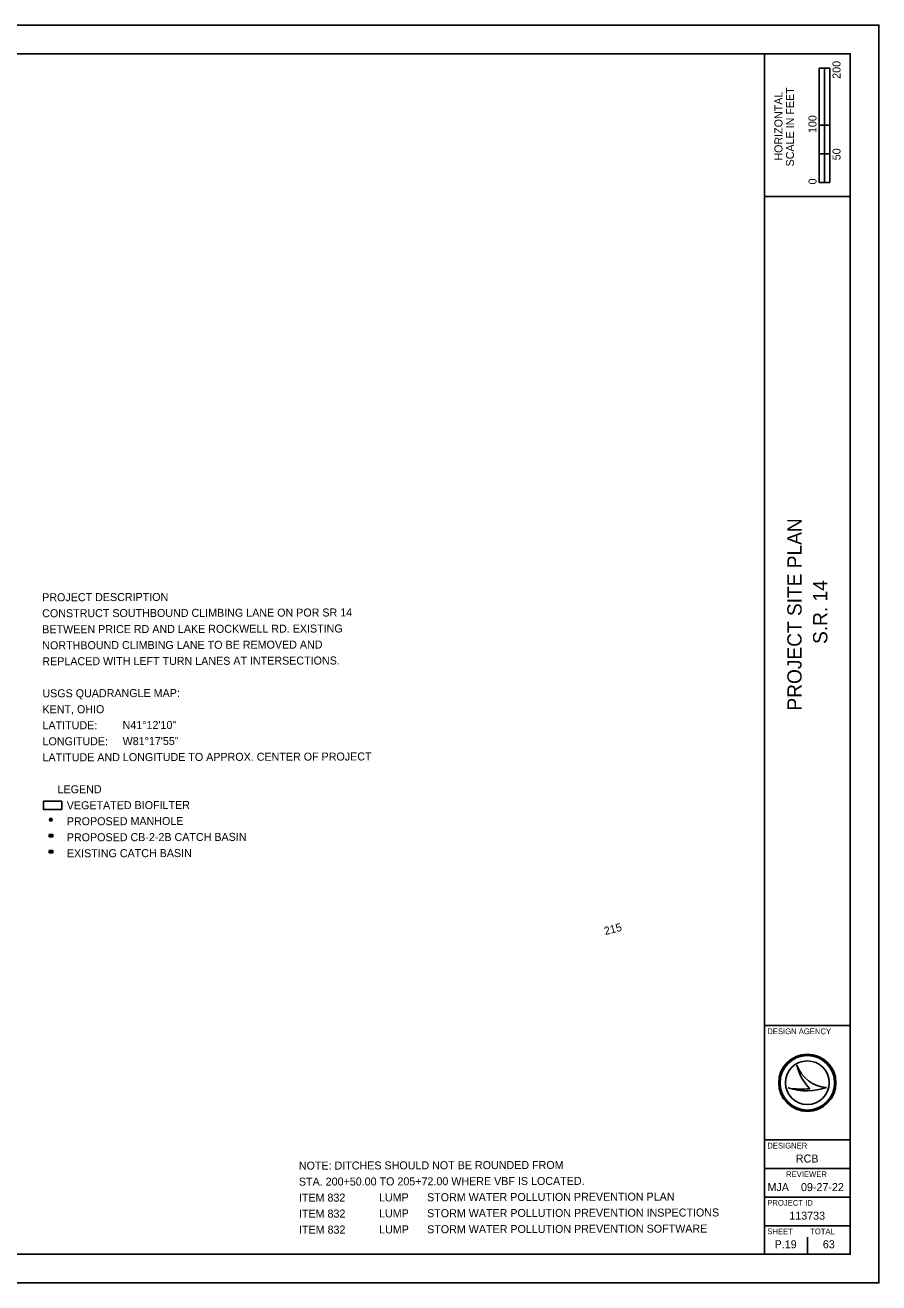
# Model space of a CAD drawing. Extents: x -4.7 to 34, y -1.1 to 22.
# Drawn here: x 19.07 to 34, y 0 to 22 of the extents above; entities that cross this region are included whole.
import ezdxf

# ---------------------------------------------------------------- set-up
doc = ezdxf.new("R2010")
doc.units = 0
for name, color, linetype in [('_CIVIL_CONSTRUCTION', 7, 'Continuous'), ('RW_X_CL_1000_Bearings', 7, 'Continuous'), ('RW_X_CL_1000_Cardinal_Points', 7, 'Continuous'), ('RW_X_CL_1000_Curve_Data', 7, 'Continuous'), ('RW_X_CL_100_Bearings', 7, 'Continuous'), ('RW_X_CL_100_Cardinal_Points', 7, 'Continuous'), ('RW_X_CL_500_Bearings', 7, 'Continuous'), ('RW_X_CL_500_Stations', 7, 'Continuous')]:
    doc.layers.add(name, color=color, linetype=linetype)

msp = doc.modelspace()

# ---------------------------------------------------------------- linework, layer by layer
at = {"layer": '_CIVIL_CONSTRUCTION'}
msp.add_lwpolyline([(0, 0), (34, 0), (34, 22), (0, 22)], close=True, dxfattribs=at)
at = {"layer": 'RW_X_CL_1000_Bearings'}
for p, q in [((19.499, 7.526), (19.531, 7.558)), ((19.499, 7.538), (19.52, 7.558)), ((19.499, 7.549), (19.509, 7.558)), ((19.51, 7.526), (19.542, 7.558)), ((19.521, 7.526), (19.553, 7.557)), ((19.533, 7.526), (19.553, 7.546)), ((19.544, 7.526), (19.553, 7.535))]:
    msp.add_line(p, q, dxfattribs=at)
for points in [[(19.493, 7.562), (19.559, 7.562), (19.559, 7.522), (19.493, 7.522)], [(19.499, 7.558), (19.553, 7.558), (19.553, 7.526), (19.499, 7.526)], [(19.499, 7.555), (19.553, 7.555), (19.553, 7.529), (19.499, 7.529)]]:
    msp.add_lwpolyline(points, close=True, dxfattribs=at)
at = {"layer": 'RW_X_CL_1000_Cardinal_Points'}
for p, q in [((19.524, 8.122), (19.524, 8.122)), ((19.524, 8.102), (19.524, 8.102)), ((19.524, 8.102), (19.524, 8.102)), ((19.524, 8.095), (19.524, 8.095)), ((19.524, 8.082), (19.524, 8.082)), ((19.499, 7.822), (19.499, 7.822)), ((19.525, 7.842), (19.525, 7.842)), ((19.525, 7.835), (19.525, 7.835)), ((19.525, 7.822), (19.525, 7.822)), ((19.525, 7.822), (19.525, 7.822)), ((19.525, 7.809), (19.525, 7.809)), ((19.525, 7.806), (19.525, 7.806)), ((19.525, 7.802), (19.525, 7.802)), ((19.552, 7.822), (19.552, 7.822)), ((19.499, 7.542), (19.499, 7.542)), ((19.526, 7.562), (19.526, 7.562)), ((19.526, 7.555), (19.526, 7.555)), ((19.526, 7.542), (19.526, 7.542)), ((19.526, 7.542), (19.526, 7.542)), ((19.526, 7.529), (19.526, 7.529)), ((19.526, 7.526), (19.526, 7.526)), ((19.526, 7.522), (19.526, 7.522)), ((19.553, 7.542), (19.553, 7.542))]:
    msp.add_line(p, q, dxfattribs=at)
msp.add_circle((19.524, 8.102), 0.02, dxfattribs=at)
at = {"layer": 'RW_X_CL_1000_Curve_Data'}
msp.add_lwpolyline([(19.392, 8.423), (19.392, 8.28), (19.712, 8.28), (19.712, 8.423)], close=True, dxfattribs=at)
at = {"layer": 'RW_X_CL_100_Bearings'}
for p, q in [((32, 0.5), (32, 21.5)), ((32, 19), (33.5, 19)), ((32, 4.5), (33.5, 4.5)), ((32, 2.5), (33.5, 2.5)), ((32, 2), (33.5, 2)), ((32, 1.5), (33.5, 1.5)), ((32, 1), (33.5, 1))]:
    msp.add_line(p, q, dxfattribs=at)
msp.add_lwpolyline([(1.5, 21.5), (33.5, 21.5), (33.5, 0.5), (1.5, 0.5)], close=True, dxfattribs=at)
at = {"layer": 'RW_X_CL_100_Cardinal_Points'}
for p, q in [((32.957, 19.25), (32.957, 21.25)), ((33.144, 21.25), (32.957, 21.25)), ((32.957, 20.25), (32.957, 21.25)), ((32.957, 21.25), (33.05, 21.25)), ((33.05, 21.25), (33.051, 21.25)), ((33.051, 21.25), (33.051, 20.25)), ((33.144, 21.25), (33.144, 19.25)), ((33.051, 20.25), (32.957, 20.25)), ((33.143, 20.25), (33.05, 20.25)), ((33.05, 20.25), (33.05, 19.75)), ((33.143, 19.75), (33.143, 20.25)), ((33.05, 19.75), (32.957, 19.75)), ((32.957, 19.75), (32.957, 19.25)), ((33.05, 19.25), (33.05, 19.75)), ((33.05, 19.75), (33.143, 19.75)), ((33.144, 19.25), (32.957, 19.25)), ((32.957, 19.25), (33.05, 19.25)), ((32.567, 3.81), (32.567, 3.81)), ((32.417, 3.41), (32.417, 3.41)), ((32.75, 3.5), (32.75, 3.5)), ((33.087, 3.419), (33.087, 3.419)), ((32.375, 0.675), (32.375, 0.675)), ((32.75, 0.5), (32.75, 0.8))]:
    msp.add_line(p, q, dxfattribs=at)
for radius in [0.5, 0.477, 0.477, 0.382]:
    msp.add_circle((32.75, 3.5), radius, dxfattribs=at)
for centre, radius, start, end in [((33.116, 3.998), 0.58, 198.9257, 198.9319), ((33.347, 3.97), 0.796, 191.6379, 191.6421), ((33.116, 3.998), 0.58, 198.9319, 267.1657), ((33.347, 3.97), 0.796, 191.6421, 226.0947), ((32.739, 4.37), 1.013, 251.4576, 290.0832), ((32.648, 4.654), 1.266, 259.4964, 259.4995), ((32.739, 4.37), 1.013, 251.4527, 251.4576), ((32.648, 4.654), 1.266, 259.4995, 276.6672)]:
    msp.add_arc(centre, radius, start, end, dxfattribs=at)
at = {"layer": 'RW_X_CL_500_Stations'}
for points in [[(19.492, 7.842), (19.559, 7.842), (19.559, 7.802), (19.492, 7.802)], [(19.499, 7.838), (19.552, 7.838), (19.552, 7.806), (19.499, 7.806)], [(19.499, 7.835), (19.552, 7.835), (19.552, 7.809), (19.499, 7.809)]]:
    msp.add_lwpolyline(points, close=True, dxfattribs=at)
for centre, radius in [((19.524, 8.102), 0.0242), ((19.524, 8.102), 0.02), ((19.524, 8.095), 0.01)]:
    msp.add_circle(centre, radius, dxfattribs=at)

# ---------------------------------------------------------------- texts
at = {"layer": 'RW_X_CL_100_Cardinal_Points'}
for s, height, rotation, p in [('200', 0.14, 90, (33.33, 21.062)), ('SCALE IN FEET', 0.14, 90, (32.517, 19.529)), ('HORIZONTAL', 0.14, 90, (32.315, 19.63)), ('100', 0.14, 90, (32.91, 20.112)), ('50', 0.14, 90, (33.33, 19.637)), ('0', 0.14, 90, (32.91, 19.214)), ('PROJECT SITE PLAN', 0.25, 90, (32.65, 10.011)), ('S.R. 14', 0.25, 90, (33.1, 11.176)), ('PROJECT DESCRIPTION', 0.14, 0.1602, (19.371, 11.922)), ('CONSTRUCT SOUTHBOUND CLIMBING LANE ON POR SR 14 ', 0.14, 0.1602, (19.371, 11.642)), ('BETWEEN PRICE RD AND LAKE ROCKWELL RD. EXISTING ', 0.14, 0.1602, (19.372, 11.362)), ('NORTHBOUND CLIMBING LANE TO BE REMOVED AND ', 0.14, 0.1602, (19.373, 11.082)), ('REPLACED WITH LEFT TURN LANES AT INTERSECTIONS.', 0.14, 0.1602, (19.374, 10.802)), ('USGS QUADRANGLE MAP:', 0.14, 0.1602, (19.375, 10.242)), ('KENT, OHIO         ', 0.14, 0.1602, (19.376, 9.962)), ('LATITUDE:', 0.14, 0.1602, (19.377, 9.682)), ('N41°12\'10" ', 0.14, 0.1602, (20.777, 9.686)), ('LONGITUDE:', 0.14, 0.1602, (19.378, 9.402)), ('W81°17\'55"', 0.14, 0.1602, (20.778, 9.406)), ('LATITUDE AND LONGITUDE TO APPROX. CENTER OF PROJECT', 0.14, 0.1602, (19.378, 9.122)), ('     LEGEND     ', 0.14, 0.1602, (19.38, 8.562)), ('VEGETATED BIOFILTER', 0.14, 0.1602, (19.801, 8.283)), ('PROPOSED MANHOLE', 0.14, 0.1602, (19.802, 8.003)), ('PROPOSED CB-2-2B CATCH BASIN', 0.14, 0.1602, (19.802, 7.723)), ('EXISTING CATCH BASIN', 0.14, 0.1602, (19.803, 7.443)), ('NOTE: DITCHES SHOULD NOT BE ROUNDED FROM ', 0.14, 0.1602, (23.859, 1.98)), ('STA. 200+50.00 TO 205+72.00 WHERE VBF IS LOCATED. ', 0.14, 0.1602, (23.86, 1.7)), ('ITEM 832', 0.14, 0.1602, (23.86, 1.42)), ('LUMP', 0.14, 0.1602, (25.26, 1.424)), ('STORM WATER POLLUTION PREVENTION PLAN', 0.14, 0.1602, (26.1, 1.427)), ('ITEM 832', 0.14, 0.1602, (23.861, 1.14)), ('LUMP', 0.14, 0.1602, (25.261, 1.144)), ('STORM WATER POLLUTION PREVENTION INSPECTIONS', 0.14, 0.1602, (26.101, 1.147)), ('ITEM 832', 0.14, 0.1602, (23.862, 0.86)), ('LUMP', 0.14, 0.1602, (25.262, 0.864)), ('STORM WATER POLLUTION PREVENTION SOFTWARE', 0.14, 0.1602, (26.102, 0.867))]:
    msp.add_text(s, height=height, rotation=rotation, dxfattribs=at).set_placement(p)
for s, height, p in [('DESIGN AGENCY', 0.1, (32.05, 4.35)), ('DESIGNER', 0.1, (32.05, 2.35)), ('RCB', 0.14, (32.549, 2.105)), ('REVIEWER', 0.1, (32.378, 1.85)), ('MJA', 0.14, (32.054, 1.605)), ('09-27-22', 0.14, (32.639, 1.605)), ('PROJECT ID', 0.1, (32.05, 1.35)), ('113733', 0.14, (32.435, 1.105)), ('SHEET', 0.1, (32.05, 0.85)), ('TOTAL', 0.1, (32.8, 0.85)), ('P.19', 0.14, (32.178, 0.605)), ('63', 0.14, (33.021, 0.605))]:
    msp.add_text(s, height=height, dxfattribs=at).set_placement(p)
at = {"layer": 'RW_X_CL_500_Bearings'}
msp.add_text('215', height=0.14, rotation=14.5381, dxfattribs=at).set_placement((29.216, 6.082))

doc.saveas('drawing.dxf')
